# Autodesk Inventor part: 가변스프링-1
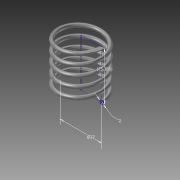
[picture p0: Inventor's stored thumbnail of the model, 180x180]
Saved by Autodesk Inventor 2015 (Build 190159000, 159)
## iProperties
Created: 2016-01
Part Number: 가변스프링-1
Material: 스테인레스 스틸
Document SubType Name: Modeling
Designer: 601-23
Density: 8 g/cm^3
Appearance: 반연마
Mass: 8.54142 g
Surface Area: 21.6554 cm^2
Volume: 1.06768 cm^3
Author: 601-23
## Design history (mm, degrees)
sketch "스케치1"
  geometry: L1 (0, 0)-(11, 0); L2 (11, 0)-(11, 25.358); L3 (11, 25.358)-(0, 25.358); L4 (0, 25.358)-(0, 0); C1 r 1 at (11, 0)
  constraints: 8 end point, 2 parallel, 1 centre point, 1 coincident, 1 horizontal, 1 perpendicular
  dimensions: "d0" = 25.35829 distance of L1.end L2.end (derived); "d1" = 22 diameter of L2 L4; "d2" = 2 diameter of C1
feature "코일1" sketch "스케치1" pitch "d3" = 5; turns "d5" = 5; dims "d4" = 25.35829 (= d0), "d6" = 0, angle "d7" = 90 deg, angle "d8" = 90 deg, "d9" = 0, "d10" = 0
node "작업 평면1"
node "작업 평면2"
sketch "스케치2"
  geometry: L1 (1, 0)-(-1, 0) reference; 1 further point
  constraints: 1 horizontal alignment
extrude "돌출1" cut sketch "스케치2" stored distance "d13" = 10; taper "d14" = 0 deg
sketch "스케치3"
  geometry: L1 (10, 0)-(12, 0) reference; 1 further point
  constraints: 1 horizontal alignment
extrude "돌출2" cut sketch "스케치3" stored distance "d15" = 10; taper "d16" = 0 deg
node "솔리드1"
node "절단 모서리 투영1"
node "절단 모서리 투영2"
other parameters: "d11" = 90 deg, "d12" = 90 deg
